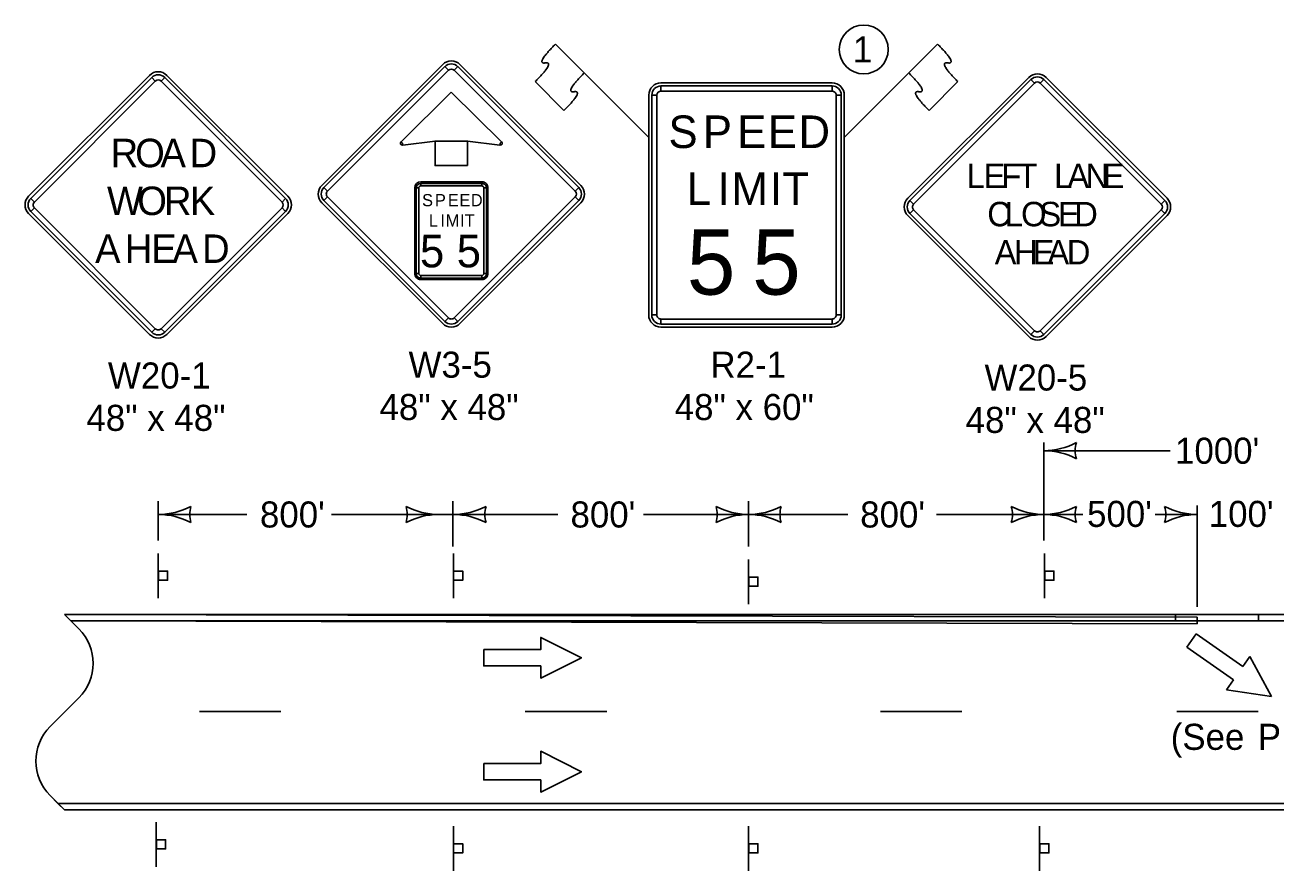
# Model space of a CAD drawing. Extents: x 10134 to 13311, y 7934 to 9733.
# Drawn here: x 10134 to 10902, y 9206 to 9725 of the extents above; entities that cross this region are included whole.
import ezdxf

# ---------------------------------------------------------------- set-up
doc = ezdxf.new("R2010")
doc.units = 0
for name, color, linetype in [('dsnCellElements', 7, 'Continuous'), ('dsnstdModifiedBlock', 7, 'Continuous'), ('dsnStdNote', 7, 'Continuous'), ('dsnStdShading', 7, 'Continuous'), ('SheetText', 7, 'Continuous')]:
    doc.layers.add(name, color=color, linetype=linetype)

msp = doc.modelspace()

# ---------------------------------------------------------------- linework, layer by layer
at = {"layer": 'dsnCellElements'}
for p, q in [((10517.28, 9655.86), (10459.96, 9713.18)), ((10459.96, 9713.18), (10477.65, 9695.49)), ((10637.28, 9655.86), (10694.6, 9713.18)), ((10694.6, 9713.18), (10676.92, 9695.49)), ((10390.8, 9700.71), (10316.56, 9626.46)), ((10392.13, 9699.38), (10394.34, 9697.17)), ((10397.87, 9697.17), (10400.08, 9699.38)), ((10475.65, 9626.46), (10401.41, 9700.71)), ((10210.9, 9694.05), (10136.65, 9619.81)), ((10212.22, 9692.73), (10214.43, 9690.52)), ((10217.97, 9690.52), (10220.18, 9692.73)), ((10295.75, 9619.81), (10221.5, 9694.05)), ((10447.59, 9690.19), (10465.26, 9672.51)), ((10465.26, 9672.51), (10447.59, 9690.19)), ((10750.52, 9692.8), (10676.28, 9618.55)), ((10706.98, 9690.19), (10689.3, 9672.51)), ((10689.3, 9672.51), (10706.98, 9690.19)), ((10751.85, 9691.47), (10754.06, 9689.26)), ((10757.6, 9689.26), (10759.8, 9691.47)), ((10835.38, 9618.55), (10761.13, 9692.8)), ((10517.28, 9681.91), (10517.28, 9546.91)), ((10519.16, 9681.91), (10522.28, 9681.91)), ((10629.78, 9689.41), (10524.78, 9689.41)), ((10524.78, 9684.41), (10524.78, 9687.54)), ((10629.78, 9687.54), (10629.78, 9684.41)), ((10632.28, 9681.91), (10635.41, 9681.91)), ((10637.28, 9546.91), (10637.28, 9681.91)), ((10366.11, 9652.41), (10365.22, 9653.29)), ((10366.26, 9651.17), (10366.11, 9652.41)), ((10426.11, 9652.41), (10425.95, 9651.17)), ((10426.99, 9653.29), (10426.11, 9652.41)), ((10414.86, 9628.66), (10377.36, 9628.66)), ((10320.09, 9622.92), (10317.88, 9625.13)), ((10373.61, 9624.91), (10373.61, 9572.41)), ((10374.54, 9624.91), (10376.11, 9624.91)), ((10377.36, 9626.16), (10377.36, 9627.72)), ((10414.86, 9627.72), (10414.86, 9626.16)), ((10416.11, 9624.91), (10417.67, 9624.91)), ((10418.61, 9572.41), (10418.61, 9624.91)), ((10474.33, 9625.13), (10472.12, 9622.92)), ((10140.19, 9616.27), (10137.98, 9618.48)), ((10294.42, 9618.48), (10292.21, 9616.27)), ((10316.56, 9615.85), (10390.8, 9541.61)), ((10317.88, 9617.18), (10320.09, 9619.39)), ((10401.41, 9541.61), (10475.65, 9615.85)), ((10472.12, 9619.39), (10474.33, 9617.18)), ((10679.81, 9615.02), (10677.6, 9617.23)), ((10834.05, 9617.23), (10831.84, 9615.02)), ((10136.65, 9609.2), (10210.9, 9534.96)), ((10137.98, 9610.53), (10140.19, 9612.74)), ((10221.5, 9534.96), (10295.75, 9609.2)), ((10292.21, 9612.74), (10294.42, 9610.53)), ((10676.28, 9607.95), (10750.52, 9533.7)), ((10677.6, 9609.27), (10679.81, 9611.48)), ((10761.13, 9533.7), (10835.38, 9607.95)), ((10831.84, 9611.48), (10834.05, 9609.27)), ((10376.11, 9572.41), (10374.54, 9572.41)), ((10377.36, 9569.59), (10377.36, 9571.16)), ((10377.36, 9568.66), (10414.86, 9568.66)), ((10414.86, 9571.16), (10414.86, 9569.59)), ((10417.67, 9572.41), (10416.11, 9572.41)), ((10394.34, 9545.14), (10392.13, 9542.93)), ((10400.08, 9542.93), (10397.87, 9545.14)), ((10522.28, 9546.91), (10519.16, 9546.91)), ((10524.78, 9541.29), (10524.78, 9544.41)), ((10629.78, 9544.41), (10629.78, 9541.29)), ((10635.41, 9546.91), (10632.28, 9546.91)), ((10214.43, 9538.49), (10212.22, 9536.28)), ((10220.18, 9536.28), (10217.97, 9538.49)), ((10524.78, 9539.41), (10629.78, 9539.41)), ((10754.06, 9537.24), (10751.85, 9535.03)), ((10759.8, 9535.03), (10757.6, 9537.24)), ((10214.99, 9235.57), (10214.99, 9208.07)), ((10397.4, 9233.04), (10397.4, 9205.54)), ((10578.57, 9233.04), (10578.57, 9205.54)), ((10757.12, 9233.04), (10757.12, 9205.54))]:
    msp.add_line(p, q, dxfattribs=at)
for points in [[(10392.13, 9699.38), (10317.88, 9625.13), (10320.09, 9622.92), (10394.34, 9697.17), (10392.13, 9699.38)], [(10474.33, 9625.13), (10400.08, 9699.38), (10397.87, 9697.17), (10472.12, 9622.92), (10474.33, 9625.13)], [(10212.22, 9692.73), (10137.98, 9618.48), (10140.19, 9616.27), (10214.43, 9690.52), (10212.22, 9692.73)], [(10294.42, 9618.48), (10220.18, 9692.73), (10217.97, 9690.52), (10292.21, 9616.27), (10294.42, 9618.48)], [(10751.85, 9691.47), (10677.6, 9617.23), (10679.81, 9615.02), (10754.06, 9689.26), (10751.85, 9691.47)], [(10834.05, 9617.23), (10759.8, 9691.47), (10757.6, 9689.26), (10831.84, 9615.02), (10834.05, 9617.23)], [(10396.11, 9683.66), (10365.22, 9653.29), (10366.11, 9652.41), (10366.26, 9651.17), (10386.11, 9653.66), (10406.11, 9653.66), (10425.95, 9651.17), (10426.11, 9652.41), (10426.99, 9653.29), (10396.11, 9683.66)], [(10519.16, 9681.91), (10519.16, 9546.91), (10522.28, 9546.91), (10522.28, 9681.91), (10519.16, 9681.91)], [(10629.78, 9687.54), (10524.78, 9687.54), (10524.78, 9684.41), (10629.78, 9684.41), (10629.78, 9687.54)], [(10635.41, 9546.91), (10635.41, 9681.91), (10632.28, 9681.91), (10632.28, 9546.91), (10635.41, 9546.91)], [(10406.11, 9638.66), (10386.11, 9638.66), (10386.11, 9653.66), (10406.11, 9653.66), (10406.11, 9638.66)], [(10374.54, 9624.91), (10374.54, 9572.41), (10376.11, 9572.41), (10376.11, 9624.91), (10374.54, 9624.91)], [(10414.86, 9627.72), (10377.36, 9627.72), (10377.36, 9626.16), (10414.86, 9626.16), (10414.86, 9627.72)], [(10417.67, 9572.41), (10417.67, 9624.91), (10416.11, 9624.91), (10416.11, 9572.41), (10417.67, 9572.41)], [(10317.88, 9617.18), (10392.13, 9542.93), (10394.34, 9545.14), (10320.09, 9619.39), (10317.88, 9617.18)], [(10400.08, 9542.93), (10474.33, 9617.18), (10472.12, 9619.39), (10397.87, 9545.14), (10400.08, 9542.93)], [(10137.98, 9610.53), (10212.22, 9536.28), (10214.43, 9538.49), (10140.19, 9612.74), (10137.98, 9610.53)], [(10220.18, 9536.28), (10294.42, 9610.53), (10292.21, 9612.74), (10217.97, 9538.49), (10220.18, 9536.28)], [(10677.6, 9609.27), (10751.85, 9535.03), (10754.06, 9537.24), (10679.81, 9611.48), (10677.6, 9609.27)], [(10759.8, 9535.03), (10834.05, 9609.27), (10831.84, 9611.48), (10757.6, 9537.24), (10759.8, 9535.03)], [(10377.36, 9569.59), (10414.86, 9569.59), (10414.86, 9571.16), (10377.36, 9571.16), (10377.36, 9569.59)], [(10524.78, 9541.29), (10629.78, 9541.29), (10629.78, 9544.41), (10524.78, 9544.41), (10524.78, 9541.29)], [(10215.09, 9219.12), (10215.09, 9224.75), (10220.71, 9224.75), (10220.71, 9219.12)], [(10397.49, 9216.59), (10397.49, 9222.22), (10403.12, 9222.22), (10403.12, 9216.59)], [(10578.67, 9216.59), (10578.67, 9222.22), (10584.29, 9222.22), (10584.29, 9216.59)], [(10757.21, 9216.59), (10757.21, 9222.22), (10762.84, 9222.22), (10762.84, 9216.59)]]:
    msp.add_lwpolyline(points, close=True, dxfattribs=at)
for centre, radius, start, end in [((10396.11, 9695.4), 7.5, 44.99999, 134.99974), ((10396.11, 9695.4), 5.62, 44.99999, 134.99974), ((10396.11, 9695.4), 2.5, 44.99999, 134.99974), ((10216.2, 9688.75), 7.5, 44.99999, 134.99974), ((10216.2, 9688.75), 5.62, 44.99999, 134.99974), ((10216.2, 9688.75), 2.5, 44.99999, 134.99974), ((10755.83, 9687.5), 7.5, 44.99999, 134.99974), ((10755.83, 9687.5), 5.62, 44.99999, 134.99974), ((10755.83, 9687.5), 2.5, 44.99999, 134.99974), ((10524.78, 9681.91), 7.5, 90.00021, 179.99985), ((10524.78, 9681.91), 5.62, 90.00021, 179.99985), ((10524.78, 9681.91), 2.5, 90.00021, 179.99985), ((10629.78, 9681.91), 7.5, 0, 90.00021), ((10629.78, 9681.91), 5.62, 0, 90.00021), ((10629.78, 9681.91), 2.5, 0, 90.00021), ((10366.11, 9652.41), 1.25, 134.99974, 277.15286), ((10426.11, 9652.41), 1.25, 262.84725, 44.9998), ((10377.36, 9624.91), 3.75, 90.00021, 179.99985), ((10414.86, 9624.91), 3.75, 0, 90.00021), ((10321.86, 9621.16), 7.5, 134.99974, 224.99995), ((10321.86, 9621.16), 5.62, 134.99974, 224.99995), ((10321.86, 9621.16), 2.5, 134.99974, 224.99995), ((10377.36, 9624.91), 2.81, 90.00021, 179.99985), ((10377.36, 9624.91), 1.25, 90.00021, 179.99985), ((10414.86, 9624.91), 2.81, 0, 90.00021), ((10414.86, 9624.91), 1.25, 0, 90.00021), ((10470.35, 9621.16), 2.5, 315.00016, 44.9998), ((10470.35, 9621.16), 5.62, 315.00016, 44.9998), ((10470.35, 9621.16), 7.5, 315.00016, 44.9998), ((10141.96, 9614.51), 7.5, 134.99974, 224.99995), ((10141.96, 9614.51), 5.62, 134.99974, 224.99995), ((10141.96, 9614.51), 2.5, 134.99974, 224.99995), ((10290.44, 9614.51), 2.5, 315.00016, 44.9998), ((10290.44, 9614.51), 5.62, 315.00016, 44.9998), ((10290.44, 9614.51), 7.5, 315.00016, 44.9998), ((10681.58, 9613.25), 7.5, 134.99974, 224.99995), ((10681.58, 9613.25), 5.62, 134.99974, 224.99995), ((10681.58, 9613.25), 2.5, 134.99974, 224.99995), ((10830.07, 9613.25), 2.5, 315.00016, 44.9998), ((10830.07, 9613.25), 5.62, 315.00016, 44.9998), ((10830.07, 9613.25), 7.5, 315.00016, 44.9998), ((10377.36, 9572.41), 3.75, 179.99985, 270.00006), ((10377.36, 9572.41), 2.81, 179.99985, 270.00006), ((10377.36, 9572.41), 1.25, 179.99985, 270.00006), ((10414.86, 9572.41), 3.75, 270.00006, 0.00027), ((10414.86, 9572.41), 2.81, 270.00006, 0.00027), ((10414.86, 9572.41), 1.25, 270.00006, 0.00027), ((10396.11, 9546.91), 2.5, 224.99995, 315.00016), ((10524.78, 9546.91), 7.5, 179.99985, 270.00006), ((10524.78, 9546.91), 5.62, 179.99985, 270.00006), ((10524.78, 9546.91), 2.5, 179.99985, 270.00006), ((10629.78, 9546.91), 7.5, 270.00006, 0.00027), ((10629.78, 9546.91), 5.62, 270.00006, 0.00027), ((10629.78, 9546.91), 2.5, 270.00006, 0.00027), ((10216.2, 9540.26), 5.62, 224.99995, 315.00016), ((10216.2, 9540.26), 2.5, 224.99995, 315.00016), ((10396.11, 9546.91), 7.5, 224.99995, 315.00016), ((10396.11, 9546.91), 5.62, 224.99995, 315.00016), ((10755.83, 9539), 2.5, 224.99995, 315.00016), ((10216.2, 9540.26), 7.5, 224.99995, 315.00016), ((10755.83, 9539), 7.5, 224.99995, 315.00016), ((10755.83, 9539), 5.62, 224.99995, 315.00016)]:
    msp.add_arc(centre, radius, start, end, dxfattribs=at)
for points in [[(10459.96, 9713.18), (10447.59, 9700.79), (10459.96, 9702.56), (10447.59, 9690.19)], [(10447.59, 9690.19), (10459.96, 9702.56), (10447.59, 9700.79), (10459.96, 9713.18)], [(10694.6, 9713.18), (10706.98, 9700.79), (10694.6, 9702.56), (10706.98, 9690.19)], [(10706.98, 9690.19), (10694.6, 9702.56), (10706.98, 9700.79), (10694.6, 9713.18)], [(10477.65, 9695.49), (10465.27, 9683.11), (10477.64, 9684.88), (10465.26, 9672.51)], [(10477.65, 9695.49), (10465.27, 9683.11), (10477.64, 9684.88), (10465.26, 9672.51)], [(10676.92, 9695.49), (10689.3, 9683.11), (10676.93, 9684.88), (10689.3, 9672.51)], [(10676.92, 9695.49), (10689.3, 9683.11), (10676.93, 9684.88), (10689.3, 9672.51)]]:
    msp.add_open_spline(points, degree=2, dxfattribs=at)
at = {"layer": 'dsnstdModifiedBlock'}
for p, q in [((10167.44, 9354.24), (10158.66, 9363.02)), ((10162.64, 9359.04), (11358.88, 9359.04)), ((10847.44, 9342.96), (10853.18, 9351.16)), ((10853.18, 9351.16), (10881.84, 9331.09)), ((10876.11, 9322.89), (10847.44, 9342.96)), ((10881.84, 9331.09), (10886.14, 9337.23)), ((10886.14, 9337.23), (10899.45, 9312.65)), ((10871.81, 9316.75), (10876.11, 9322.89)), ((10899.45, 9312.65), (10871.81, 9316.75)), ((10149.87, 9294.25), (10167.44, 9311.82)), ((10158.66, 9243.04), (10149.87, 9251.83)), ((10154.68, 9247.02), (11772.83, 9247.02))]:
    msp.add_line(p, q, dxfattribs=at)
for points in [[(10241.49, 9303.44), (10291.48, 9303.44)], [(10441.46, 9303.44), (10491.45, 9303.44)], [(10659.42, 9303.44), (10709.42, 9303.44)], [(10841.39, 9303.44), (10891.38, 9303.44)]]:
    msp.add_lwpolyline(points, dxfattribs=at)
for centre, start, end in [((10146.23, 9333.03), 315, 45), ((10171.08, 9273.04), 135, 225)]:
    msp.add_arc(centre, 30, start, end, dxfattribs=at)
at = {"layer": 'dsnStdNote'}
msp.add_circle((10649.23, 9709.95), 15, dxfattribs=at)
at = {"layer": 'dsnStdShading'}
for p, q in [((10840.66, 9363.04), (10158.66, 9363.04)), ((10158.66, 9363.04), (10167.44, 9354.24)), ((10853.86, 9361.34), (10158.66, 9363.04)), ((10840.66, 9359.04), (10840.66, 9363.04)), ((10891.48, 9363.04), (10840.66, 9363.04)), ((10840.66, 9363.04), (10840.66, 9359.04)), ((10853.86, 9357.34), (10853.86, 9361.34)), ((11083.44, 9363.04), (10891.48, 9363.04)), ((10891.48, 9363.04), (10891.48, 9359.04)), ((10891.48, 9359.04), (10891.48, 9363.04)), ((10162.65, 9359.04), (10853.86, 9357.34)), ((10840.66, 9359.04), (10891.48, 9359.04)), ((10891.48, 9359.04), (11083.44, 9359.04)), ((10167.44, 9311.82), (10149.87, 9294.25)), ((10149.87, 9251.83), (10154.66, 9247.04)), ((11538.19, 9247.04), (10154.66, 9247.04)), ((10154.66, 9247.04), (10158.66, 9243.04)), ((10154.66, 9247.04), (10989.42, 9247.04)), ((10158.66, 9243.04), (11564.95, 9243.04)), ((10158.66, 9243.04), (11536.47, 9243.04))]:
    msp.add_line(p, q, dxfattribs=at)
for points in [[(10158.66, 9363.04), (10162.64, 9359.05), (10162.65, 9359.04)], [(10989.42, 9359.04), (10891.48, 9359.04), (10840.66, 9359.04)], [(10154.66, 9247.04), (10154.66, 9247.04)], [(10154.66, 9247.04), (10154.66, 9247.04)]]:
    msp.add_lwpolyline(points, dxfattribs=at)
for centre, start, end in [((10146.23, 9333.03), 315, 45), ((10171.08, 9273.04), 135, 225)]:
    msp.add_arc(centre, 30, start, end, dxfattribs=at)
at = {"layer": 'SheetText'}
for p, q in [((10759.77, 9408.54), (10759.77, 9468.58)), ((10759.56, 9463.58), (10837.22, 9463.58)), ((10216.2, 9408.54), (10216.2, 9432.55)), ((10397.01, 9404.81), (10397.01, 9432.55)), ((10578.59, 9404.81), (10578.59, 9432.55)), ((10853.86, 9367.77), (10853.86, 9430.02)), ((10270.65, 9424.43), (10219, 9424.43)), ((10322.58, 9424.43), (10397.01, 9424.43)), ((10461.46, 9424.43), (10397.01, 9424.43)), ((10514.15, 9424.43), (10578.59, 9424.43)), ((10639.37, 9424.43), (10578.59, 9424.43)), ((10693.79, 9424.43), (10759.56, 9424.43)), ((10760.37, 9424.43), (10783.66, 9424.43)), ((10828.09, 9424.43), (10853.86, 9424.43)), ((10216.2, 9400.54), (10216.2, 9373.04)), ((10397.4, 9400.54), (10397.4, 9373.04)), ((10760.22, 9400.54), (10760.22, 9373.04)), ((10578.59, 9396.81), (10578.59, 9369.31))]:
    msp.add_line(p, q, dxfattribs=at)
for points in [[(10216.29, 9384.09), (10216.29, 9389.72), (10221.92, 9389.72), (10221.92, 9384.09)], [(10397.49, 9384.09), (10397.49, 9389.72), (10403.12, 9389.72), (10403.12, 9384.09)], [(10578.69, 9380.36), (10578.69, 9385.98), (10584.31, 9385.98), (10584.31, 9380.36)], [(10760.31, 9384.09), (10760.31, 9389.72), (10765.94, 9389.72), (10765.94, 9384.09)]]:
    msp.add_lwpolyline(points, close=True, dxfattribs=at)
for points in [[(10415.96, 9341.5), (10415.96, 9331.5), (10450.96, 9331.5), (10450.96, 9324), (10475.96, 9336.5), (10450.96, 9349), (10450.96, 9341.5), (10415.96, 9341.5)], [(10415.96, 9271.51), (10415.96, 9261.51), (10450.96, 9261.51), (10450.96, 9254.01), (10475.96, 9266.51), (10450.96, 9279.01), (10450.96, 9271.51), (10415.96, 9271.51)]]:
    msp.add_lwpolyline(points, dxfattribs=at)
for centre, radius, start, end in [((10759.77, 9506.08), 42.5, 270, 298.07249), ((10795.4, 9463.58), 16.42, 162.26665, 197.73335), ((10759.77, 9421.08), 42.5, 61.92751, 90), ((10216.31, 9466.93), 42.5, 270, 298.07249), ((10251.95, 9424.43), 16.42, 162.26665, 197.73335), ((10352.66, 9424.43), 16.42, 342.26665, 17.73335), ((10388.3, 9466.93), 42.5, 241.92751, 270), ((10397.4, 9466.93), 42.5, 270, 298.07249), ((10433.03, 9424.43), 16.42, 162.26665, 197.73335), ((10542.94, 9424.43), 16.42, 342.26665, 17.73335), ((10578.57, 9466.93), 42.5, 241.92751, 270), ((10578.57, 9466.93), 42.5, 270, 298.07249), ((10614.21, 9424.43), 16.42, 162.26665, 197.73335), ((10724.13, 9424.43), 16.42, 342.26665, 17.73335), ((10759.77, 9466.93), 42.5, 241.92751, 270), ((10759.77, 9466.93), 42.5, 270, 298.07249), ((10795.4, 9424.43), 16.42, 162.26665, 197.73335), ((10818.23, 9424.43), 16.42, 342.26665, 17.73335), ((10853.86, 9466.93), 42.5, 241.92751, 270), ((10216.31, 9381.93), 42.5, 61.92751, 90), ((10388.3, 9381.93), 42.5, 90, 118.07249), ((10397.4, 9381.93), 42.5, 61.92751, 90), ((10578.57, 9381.93), 42.5, 90, 118.07249), ((10578.57, 9381.93), 42.5, 61.92751, 90), ((10759.77, 9381.93), 42.5, 90, 118.07249), ((10759.77, 9381.93), 42.5, 61.92751, 90), ((10853.86, 9381.93), 42.5, 90, 118.07249)]:
    msp.add_arc(centre, radius, start, end, dxfattribs=at)

# ---------------------------------------------------------------- texts
at = {"layer": 'dsnCellElements'}
for s, height, p in [('S', 20, (10529.41, 9649.41)), ('P', 20, (10550.5, 9649.41)), ('E', 20, (10571.6, 9649.41)), ('E', 20, (10590.41, 9649.41)), ('D', 20, (10609.22, 9649.41)), ('R', 17.5, (10187.04, 9637.63)), ('O', 17.5, (10202.05, 9637.63)), ('A', 17.5, (10217.6, 9637.63)), ('D', 17.5, (10235.48, 9637.63)), ('L', 15, (10712.3, 9624.81)), ('E', 15, (10722.75, 9624.81)), ('F', 15, (10733.65, 9624.81)), ('T', 15, (10743.59, 9624.81)), ('L', 15, (10766.09, 9624.81)), ('A', 15, (10774.19, 9624.81)), ('N', 15, (10785.37, 9624.81)), ('E', 15, (10795.81, 9624.81)), ('L', 20, (10540.66, 9614.41)), ('I', 20, (10559.47, 9614.41)), ('M', 20, (10568.06, 9614.41)), ('I', 20, (10591.66, 9614.41)), ('T', 20, (10599.22, 9614.41)), ('W', 17.5, (10184.75, 9608.26)), ('O', 17.5, (10203.35, 9608.26)), ('R', 17.5, (10219.75, 9608.26)), ('K', 17.5, (10235.61, 9608.26)), ('S', 7.5, (10378.15, 9613.66)), ('P', 7.5, (10386.06, 9613.66)), ('E', 7.5, (10393.97, 9613.66)), ('E', 7.5, (10401.03, 9613.66)), ('D', 7.5, (10408.08, 9613.66)), ('C', 15, (10725.04, 9601.38)), ('L', 15, (10735.78, 9601.38)), ('O', 15, (10745.81, 9601.38)), ('S', 15, (10757.02, 9601.38)), ('E', 15, (10768.38, 9601.38)), ('D', 15, (10778.41, 9601.38)), ('L', 7.5, (10382.37, 9601.16)), ('I', 7.5, (10389.43, 9601.16)), ('M', 7.5, (10392.65, 9601.16)), ('I', 7.5, (10401.5, 9601.16)), ('T', 7.5, (10404.33, 9601.16)), ('5', 40, (10540.66, 9559.41)), ('5', 40, (10580.78, 9559.41)), ('A', 17.5, (10177.48, 9578.88)), ('H', 17.5, (10195.68, 9578.88)), ('E', 17.5, (10211.91, 9578.88)), ('A', 17.5, (10224.96, 9578.88)), ('D', 17.5, (10243.16, 9578.88)), ('5', 20, (10376.86, 9576.16)), ('5', 20, (10399.42, 9576.16)), ('A', 15, (10729.59, 9577.94)), ('H', 15, (10741.47, 9577.94)), ('E', 15, (10752.8, 9577.94)), ('A', 15, (10761.98, 9577.94)), ('D', 15, (10773.87, 9577.94))]:
    msp.add_text(s, height=height, dxfattribs=at).set_placement(p)
at = {"layer": 'dsnStdNote'}
msp.add_text('1', height=16, dxfattribs=at).set_placement((10642.53, 9701.95))
at = {"layer": 'SheetText'}
for s, p in [('W3-5', (10369.86, 9508.41)), ('R2-1', (10555.12, 9508.41)), ('W20-1', (10185.35, 9501.76)), ('W20-5', (10723.36, 9500.51)), ('48" x 48"', (10352.04, 9482.41)), ('48" x 60"', (10533.21, 9482.41)), ('48" x 48"', (10172.13, 9475.76)), ('48" x 48"', (10711.76, 9474.51)), ("1000'", (10840.3, 9455.58)), ("800'", (10278.65, 9416.43)), ("800'", (10469.24, 9416.43)), ("800'", (10647.06, 9416.43)), ("500'", (10786.3, 9416.8)), ("100'", (10861, 9416.8)), ('(See ', (10837.64, 9279.91)), ('PM-111', (10891.06, 9279.91))]:
    msp.add_text(s, height=16, dxfattribs=at).set_placement(p)

doc.saveas('drawing.dxf')
